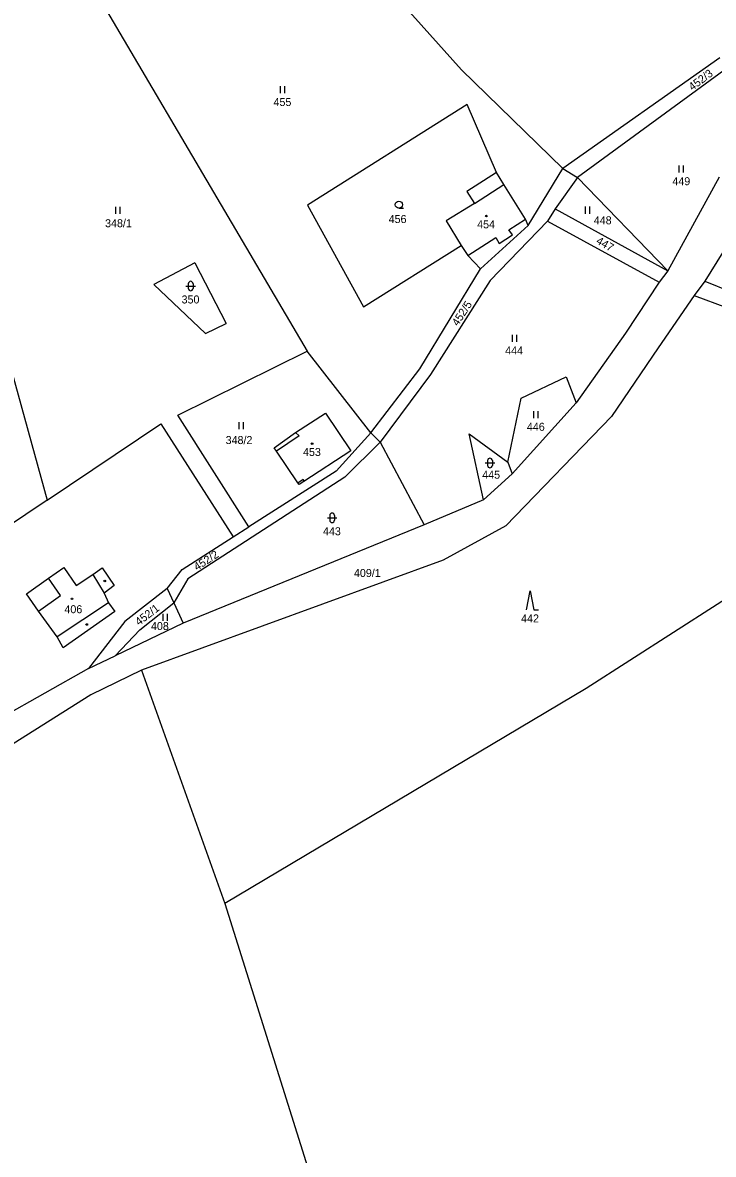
# Model space of a CAD drawing. Extents: x -670359 to -668019, y -978807 to -976674.
# Drawn here: x -669025.8 to -668879.1, y -977399.4 to -977159.1 of the extents above; entities that cross this region are included whole.
import ezdxf

# ---------------------------------------------------------------- set-up
doc = ezdxf.new("R2010")
doc.units = 0
for name, color, linetype in [('Hranice parcel', 7, 'Continuous'), ('Parcelní čísla', 7, 'Continuous'), ('Vnitřní kresba', 7, 'Continuous'), ('Značky budov', 7, 'Continuous'), ('Značky kultur', 7, 'Continuous')]:
    doc.layers.add(name, color=color, linetype=linetype)

msp = doc.modelspace()

# ---------------------------------------------------------------- linework, layer by layer
at = {"layer": 'Hranice parcel'}
msp.add_line((-668911.08, -977190.06), (-668907.97, -977191.98), dxfattribs=at)
for points in [[(-668932.58, -977169.12), (-668980.33, -977115.78)], [(-669025.76, -977126.29), (-668965.38, -977228.83)], [(-668847.41, -977160.07), (-668880.9, -977213.98)], [(-668877.7, -977166.55), (-668911.08, -977190.06)], [(-668911.08, -977190.06), (-668932.58, -977169.12)], [(-668876.1, -977168.71), (-668907.97, -977191.98)], [(-668931.37, -977176.48), (-668965.31, -977197.83)], [(-668925.15, -977190.9), (-668931.37, -977176.48)], [(-668925.15, -977190.9), (-668931.44, -977194.96)], [(-668923.58, -977193.44), (-668925.15, -977190.9)], [(-668918.41, -977202.2), (-668911.08, -977190.06)], [(-668907.97, -977191.98), (-668912.71, -977198.61)], [(-668907.97, -977191.98), (-668888.74, -977211.8)], [(-668877.86, -977191.91), (-668888.74, -977211.8)], [(-668931.44, -977194.96), (-668929.84, -977197.52)], [(-668918.97, -977200.84), (-668923.58, -977193.44)], [(-668965.31, -977197.83), (-668953.38, -977219.46)], [(-668929.84, -977197.52), (-668935.86, -977201.19)], [(-668912.71, -977198.61), (-668914.32, -977201.25)], [(-668912.71, -977198.61), (-668888.74, -977211.8)], [(-668935.86, -977201.19), (-668932.68, -977206.4)], [(-668928.53, -977211.37), (-668918.41, -977202.2)], [(-668914.32, -977201.25), (-668926.46, -977213.86)], [(-668918.41, -977202.2), (-668918.97, -977200.84)], [(-668914.32, -977201.25), (-668890.59, -977214.19)], [(-669035.72, -977206.03), (-669020.61, -977260.48)], [(-668953.38, -977219.46), (-668932.68, -977206.4)], [(-668932.68, -977206.4), (-668931.25, -977208.55)], [(-668989.21, -977210.08), (-668997.96, -977214.7)], [(-668989.21, -977210.08), (-668982.61, -977222.98)], [(-668931.25, -977208.55), (-668928.53, -977211.37)], [(-668941.41, -977232.62), (-668928.53, -977211.37)], [(-668888.74, -977211.8), (-668890.59, -977214.19)], [(-668997.96, -977214.7), (-668986.94, -977225.13)], [(-668926.46, -977213.86), (-668939.17, -977233.82)], [(-668890.59, -977214.19), (-668897.75, -977225.06)], [(-668880.9, -977213.98), (-668883.15, -977217.02)], [(-668880.9, -977213.98), (-668875.3, -977216.24)], [(-668883.15, -977217.02), (-668890.79, -977228.12)], [(-668883.15, -977217.02), (-668876.27, -977219.6)], [(-668986.94, -977225.13), (-668982.61, -977222.98)], [(-668897.75, -977225.06), (-668908.21, -977239.83)], [(-668992.86, -977242.48), (-668965.38, -977228.83)], [(-668951.86, -977246.19), (-668965.38, -977228.83)], [(-668890.79, -977228.12), (-668900.69, -977242.73)], [(-668951.86, -977246.19), (-668941.41, -977232.62)], [(-668939.17, -977233.82), (-668949.87, -977248.19)], [(-668919.89, -977238.84), (-668910.35, -977234.3)], [(-668910.35, -977234.3), (-668908.21, -977239.83)], [(-668922.74, -977252.43), (-668919.89, -977238.84)], [(-668908.21, -977239.83), (-668921.79, -977254.91)], [(-668977.74, -977266.16), (-668992.86, -977242.48)], [(-668967.88, -977246.14), (-668961.5, -977242)], [(-668961.5, -977242), (-668956.12, -977250.02)], [(-668900.69, -977242.73), (-668923.19, -977265.95)], [(-669020.61, -977260.48), (-668996.44, -977244.26)], [(-668996.44, -977244.26), (-668981.11, -977268.31)], [(-668972.39, -977249.4), (-668967.88, -977246.14)], [(-668959.18, -977254.33), (-668951.86, -977246.19)], [(-668951.86, -977246.19), (-668949.87, -977248.19)], [(-668949.87, -977248.19), (-668957.34, -977255.61)], [(-668949.87, -977248.19), (-668940.48, -977265.74)], [(-668927.89, -977260.42), (-668930.97, -977246.41)], [(-668930.97, -977246.41), (-668922.74, -977252.43)], [(-668971.89, -977250.13), (-668972.39, -977249.4)], [(-668967.35, -977256.79), (-668971.89, -977250.13)], [(-668956.12, -977250.02), (-668966.07, -977256.55)], [(-668922.74, -977252.43), (-668921.79, -977254.91)], [(-668957.34, -977255.61), (-668990.72, -977277.2)], [(-668959.18, -977254.33), (-668977.74, -977266.16)], [(-668921.79, -977254.91), (-668927.89, -977260.42)], [(-668967.07, -977257.2), (-668967.35, -977256.79)], [(-668966.07, -977256.55), (-668967.07, -977257.2)], [(-669020.61, -977260.48), (-669066.43, -977291.24)], [(-668927.89, -977260.42), (-668940.48, -977265.74)], [(-668940.48, -977265.74), (-668991.71, -977286.64)], [(-668981.11, -977268.31), (-668977.74, -977266.16)], [(-668923.19, -977265.95), (-668936.5, -977273.27)], [(-668991.92, -977275.2), (-668981.11, -977268.31)], [(-668859.71, -977270.77), (-668906.09, -977300.48)], [(-669020.3, -977277.1), (-669017.1, -977274.8)], [(-669017.1, -977274.8), (-669014.43, -977278.66)], [(-669010.91, -977276.28), (-669008.89, -977274.91)], [(-669008.89, -977274.91), (-669006.34, -977278.6)], [(-668936.5, -977273.27), (-669000.55, -977296.62)], [(-669025, -977280.4), (-669020.3, -977277.1)], [(-669014.43, -977278.66), (-669010.91, -977276.28)], [(-668995.13, -977279.27), (-668991.92, -977275.2)], [(-668990.72, -977277.2), (-668993.7, -977282.32)], [(-669006.34, -977278.6), (-669008.51, -977280.27)], [(-668995.13, -977279.27), (-669004.12, -977286.29)], [(-668995.13, -977279.27), (-668993.7, -977282.32)], [(-669022.45, -977284.08), (-669025, -977280.4)], [(-669008.51, -977280.27), (-669007.55, -977282.28)], [(-669007.55, -977282.28), (-669006.2, -977284.12)], [(-669000.93, -977288.06), (-668993.7, -977282.32)], [(-668993.7, -977282.32), (-668991.71, -977286.64)], [(-669018.47, -977289.53), (-669022.45, -977284.08)], [(-669006.2, -977284.12), (-669017.19, -977291.85)], [(-669004.12, -977286.29), (-669011.84, -977296.27)], [(-668991.71, -977286.64), (-669006.15, -977293.56)], [(-669017.19, -977291.85), (-669018.47, -977289.53)], [(-669006.15, -977293.56), (-669000.93, -977288.06)], [(-669011.84, -977296.27), (-669006.15, -977293.56)], [(-669011.84, -977296.27), (-669039.76, -977311.95)], [(-669000.55, -977296.62), (-669011.3, -977301.87)], [(-669000.55, -977296.62), (-668982.87, -977346.19)], [(-668906.09, -977300.48), (-668982.87, -977346.19)], [(-669011.3, -977301.87), (-669045.72, -977323.54)], [(-668982.87, -977346.19), (-668939.25, -977485.08)]]:
    msp.add_lwpolyline(points, dxfattribs=at)
at = {"layer": 'Vnitřní kresba'}
for points in [[(-668929.84, -977197.52), (-668923.58, -977193.44)], [(-668922.5, -977203.07), (-668918.97, -977200.84)], [(-668931.25, -977208.55), (-668925.3, -977204.74)], [(-668925.3, -977204.74), (-668924.59, -977206)], [(-668924.59, -977206), (-668921.78, -977204.19)], [(-668921.78, -977204.19), (-668922.5, -977203.07)], [(-668967.88, -977246.14), (-668967.05, -977246.86)], [(-668967.05, -977246.86), (-668971.89, -977250.13)], [(-668967.35, -977256.79), (-668966.23, -977256.07)], [(-668966.23, -977256.07), (-668966.07, -977256.55)], [(-669017.8, -977280.73), (-669020.3, -977277.1)], [(-669010.91, -977276.28), (-669008.51, -977280.27)], [(-669022.45, -977284.08), (-669017.8, -977280.73)], [(-669007.55, -977282.28), (-669018.47, -977289.53)]]:
    msp.add_lwpolyline(points, dxfattribs=at)
at = {"layer": 'Značky budov'}
for centre in [(-668927.3, -977200.17), (-668964.32, -977248.52), (-669015.32, -977281.46)]:
    msp.add_circle(centre, 0.175, dxfattribs=at)
at = {"layer": 'Značky kultur'}
for p, q in [((-668971.09, -977172.6), (-668971.09, -977174.1)), ((-668970.09, -977174.1), (-668970.09, -977172.6)), ((-668886.39, -977189.42), (-668886.39, -977190.92)), ((-668885.39, -977190.92), (-668885.39, -977189.42)), ((-668906.33, -977198.17), (-668906.33, -977199.67)), ((-668905.33, -977199.67), (-668905.33, -977198.17)), ((-669006.07, -977198.22), (-669006.07, -977199.72)), ((-669005.07, -977199.72), (-669005.07, -977198.22)), ((-668945.89, -977198.5), (-668944.89, -977198.5)), ((-668991.12, -977215.03), (-668989.12, -977215.03)), ((-668990.62, -977214.53), (-668990.62, -977215.53)), ((-668989.62, -977214.53), (-668989.62, -977215.53)), ((-668921.84, -977225.36), (-668921.84, -977226.86)), ((-668920.84, -977226.86), (-668920.84, -977225.36)), ((-668917.3, -977241.57), (-668917.3, -977243.07)), ((-668916.3, -977243.07), (-668916.3, -977241.57)), ((-668979.91, -977243.94), (-668979.91, -977245.44)), ((-668978.91, -977245.44), (-668978.91, -977243.94)), ((-668927.53, -977252.61), (-668925.53, -977252.61)), ((-668927.03, -977252.11), (-668927.03, -977253.11)), ((-668926.03, -977252.11), (-668926.03, -977253.11)), ((-668961.08, -977264.26), (-668959.08, -977264.26)), ((-668960.58, -977263.76), (-668960.58, -977264.76)), ((-668959.58, -977263.76), (-668959.58, -977264.76)), ((-668996.03, -977284.61), (-668996.03, -977286.11)), ((-668995.03, -977286.11), (-668995.03, -977284.61))]:
    msp.add_line(p, q, dxfattribs=at)
msp.add_lwpolyline([(-668918.74, -977283.77), (-668917.99, -977279.77), (-668917.24, -977283.77), (-668916.24, -977283.77)], dxfattribs=at)
for centre, radius in [((-668945.89, -977197.75), 0.75), ((-668927.3, -977200.17), 0.175), ((-668964.32, -977248.52), 0.175), ((-669008.36, -977277.67), 0.175), ((-669015.32, -977281.46), 0.175), ((-669012.19, -977286.91), 0.175)]:
    msp.add_circle(centre, radius, dxfattribs=at)
for centre, start, end in [((-668990.12, -977214.53), 0, 180), ((-668990.12, -977215.53), 180, 0), ((-668926.53, -977252.11), 0, 180), ((-668926.53, -977253.11), 180, 0), ((-668960.08, -977263.76), 0, 180), ((-668960.08, -977264.76), 180, 0)]:
    msp.add_arc(centre, 0.5, start, end, dxfattribs=at)

# ---------------------------------------------------------------- texts
at = {"layer": 'Parcelní čísla'}
for s, rotation, p in [('452/3', 36.9, (-668883.55, -977173.63)), ('447', 330.0015, (-668904.14, -977205.89)), ('452/5', 56.7, (-668933.36, -977223.67)), ('452/2', 33.0024, (-668988.77, -977275.56)), ('452/1', 37.2995, (-669001.11, -977287.24))]:
    msp.add_text(s, height=1.7, rotation=rotation, dxfattribs=at).set_placement(p)
for s, p in [('455', (-668972.52, -977176.8)), ('449', (-668887.78, -977193.62)), ('456', (-668948.06, -977201.65)), ('448', (-668904.48, -977201.92)), ('348/1', (-669008.3, -977202.54)), ('454', (-668929.26, -977202.77)), ('350', (-668992.05, -977218.73)), ('444', (-668923.3, -977229.56)), ('446', (-668918.69, -977245.77)), ('348/2', (-668982.69, -977248.59)), ('453', (-668966.25, -977251.12)), ('445', (-668928.18, -977255.95)), ('443', (-668962.01, -977267.96)), ('409/1', (-668955.43, -977276.82)), ('406', (-669016.94, -977284.52)), ('408', (-668998.55, -977288.09)), ('442', (-668919.92, -977286.47))]:
    msp.add_text(s, height=1.7, dxfattribs=at).set_placement(p)

doc.saveas('drawing.dxf')
